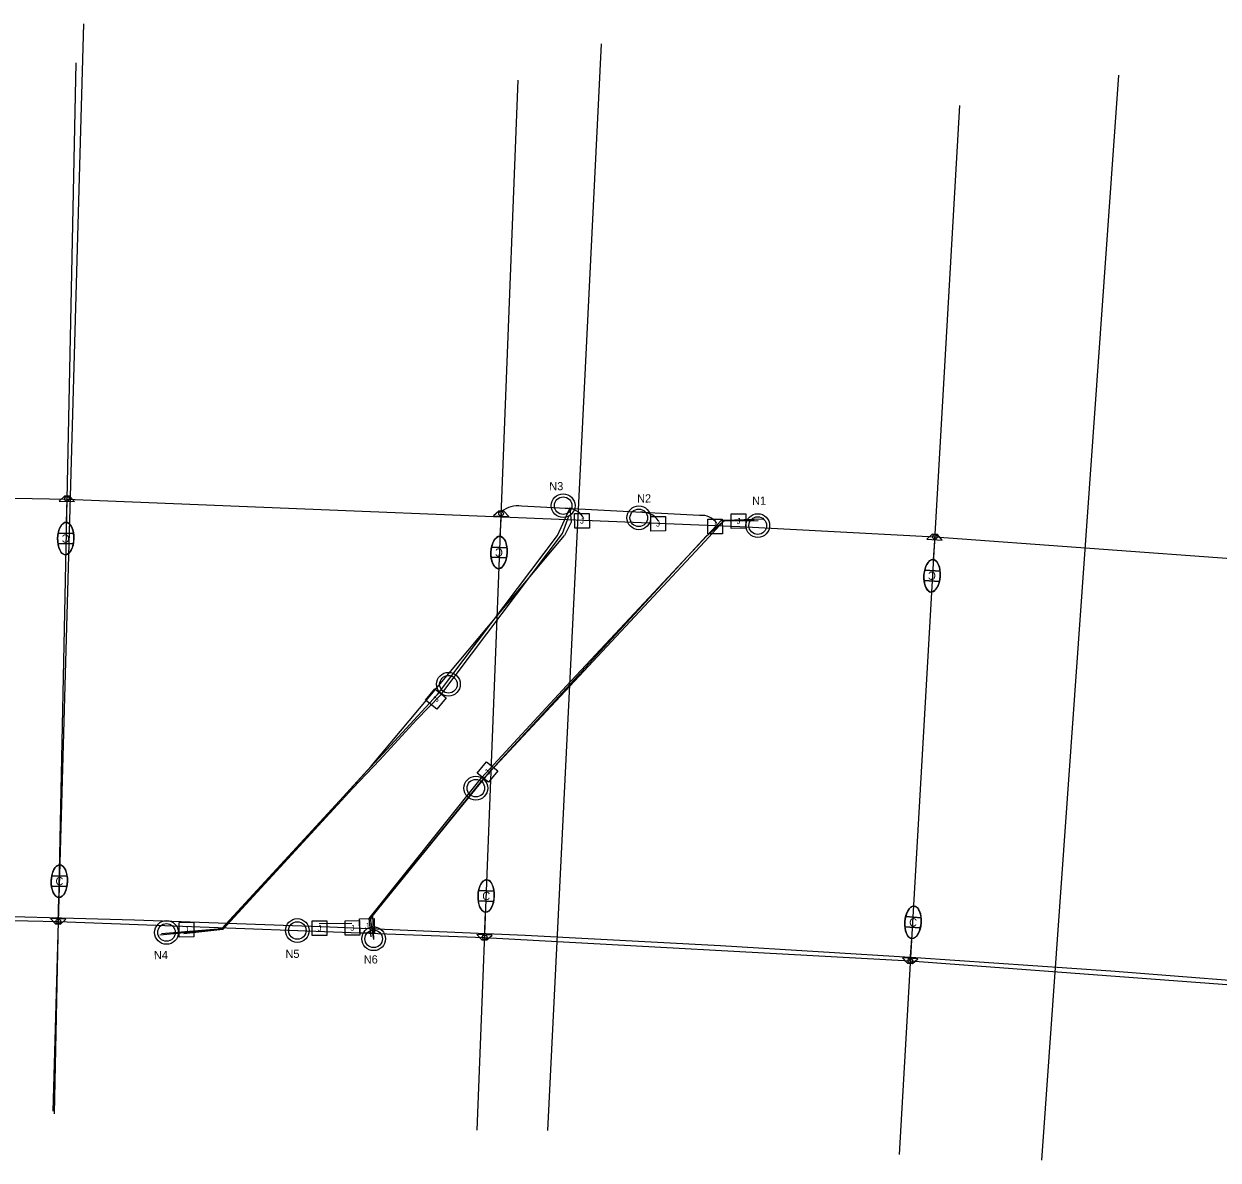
# Model space of a CAD drawing. Extents: x 915723 to 927758, y 636394 to 638609.
# Drawn here: x 923618 to 924200, y 636826 to 637381 of the extents above; entities that cross this region are included whole.
import ezdxf

# ---------------------------------------------------------------- set-up
doc = ezdxf.new("R2010")
doc.units = 0
for name, color, linetype in [('ConduitBM', 7, 'Continuous'), ('ConduitJB', 7, 'Continuous'), ('ConduitOT', 7, 'Continuous'), ('DrShaftConc', 7, 'Continuous'), ('Masonry_h', 7, 'Continuous'), ('Miscellaneous0', 7, 'Continuous'), ('Miscellaneous1', 7, 'Continuous'), ('Miscellaneous2', 7, 'Continuous'), ('PoleLight', 7, 'Continuous'), ('PullBox', 7, 'Continuous'), ('SchemElectricProp', 7, 'Continuous'), ('TextStructuresLabel', 7, 'Continuous')]:
    doc.layers.add(name, color=color, linetype=linetype)

msp = doc.modelspace()

# ---------------------------------------------------------------- linework, layer by layer
at = {"layer": 'ConduitBM'}
for p, q in [((923426.79, 637152.37), (923638.75, 637148.77)), ((923638.75, 637148.77), (923967.04, 637135.41)), ((923967.04, 637135.41), (924062.22, 637130.27)), ((924062.22, 637130.27), (924273.78, 637114.85)), ((923426.26, 636946.7), (923634.53, 636942.76)), ((923634.53, 636942.76), (923842.5, 636934.93)), ((923842.5, 636934.93), (924050.24, 636923.47)), ((924050.24, 636923.47), (924257, 636908.15))]:
    msp.add_line(p, q, dxfattribs=at)
at = {"layer": 'ConduitJB'}
for p, q in [((923947.46, 637140.78), (923860.55, 637145.32)), ((923714.85, 636938.71), (923778.24, 637007.75)), ((923761.78, 636941.71), (923777.8, 636941.86)), ((923714.85, 636938.71), (923695.74, 636936.7))]:
    msp.add_line(p, q, dxfattribs=at)
for points in [[(923778.24, 637007.75), (923791.47, 637021.58), (923809.32, 637041.11), (923821.22, 637053.21), (923880.56, 637132.02), (923883.82, 637140.88)], [(923787.24, 636935.16), (923786.18, 636944.08), (923840.97, 637012.72), (923882.53, 637057.68), (923958.1, 637138.5), (923974.12, 637138.81)]]:
    msp.add_lwpolyline(points, dxfattribs=at)
for centre, radius, start, end in [((923858.88, 637132.2), 13.23, 82.754, 127.84057), ((923882.73, 637134.92), 9.32, 26.94918, 94.93479), ((923919.61, 637133.13), 9.21, 33.12166, 96.26256), ((923948.34, 637131.61), 9.21, 34.45118, 95.45942)]:
    msp.add_arc(centre, radius, start, end, dxfattribs=at)
at = {"layer": 'DrShaftConc'}
for p, q in [((923646.82, 637380.54), (923631.93, 636850.18)), ((923899.44, 637370.74), (923873.21, 636840.82)), ((924151.8, 637355.54), (924114.23, 636826.3))]:
    msp.add_line(p, q, dxfattribs=at)
msp.add_lwpolyline([(921831.32, 636923.01), (923099.42, 636947.08), (923099.42, 636947.08), (923194.81, 636948.49), (923290.21, 636949.1), (923385.61, 636948.91), (923481.01, 636947.93), (923576.4, 636946.14), (923671.76, 636943.55), (923767.11, 636940.16), (923862.42, 636935.97), (923957.69, 636930.98), (924052.92, 636925.2), (924148.09, 636918.61), (924243.21, 636911.23)], dxfattribs=at)
at = {"layer": 'Masonry_h'}
for p, q in [((923643.12, 637361.51), (923632.6, 636848.94)), ((923858.78, 637353.12), (923838.84, 636840.91)), ((924074.19, 637340.78), (924044.87, 636829.11))]:
    msp.add_line(p, q, dxfattribs=at)
at = {"layer": 'Miscellaneous0'}
for points in [[(923684.95, 636936.92), (923714.33, 636939.24), (923819.62, 637053.46), (923878.12, 637131.01), (923884.15, 637144.22)], [(923976.03, 637138.12), (923959.14, 637137.96), (923949.96, 637128.12), (923840.83, 637011.12), (923786.72, 636944.11), (923788.4, 636933.92)]]:
    msp.add_lwpolyline(points, dxfattribs=at)
at = {"layer": 'Miscellaneous1'}
for centre, radius in [((923880.87, 637145.54), 5.79), ((923880.87, 637145.54), 4.29), ((923917.77, 637139.61), 5.79), ((923917.77, 637139.61), 4.29), ((923975.82, 637135.81), 5.79), ((923975.82, 637135.81), 4.29), ((923824.91, 637058.42), 5.79), ((923824.91, 637058.42), 4.29), ((923838.26, 637007.73), 5.79), ((923838.26, 637007.73), 4.29), ((923687.37, 636937.36), 5.79), ((923687.37, 636937.36), 4.29), ((923751.2, 636938.29), 5.79), ((923751.2, 636938.29), 4.29), ((923788.41, 636934.26), 5.79), ((923788.41, 636934.26), 4.29)]:
    msp.add_circle(centre, radius, dxfattribs=at)
at = {"layer": 'Miscellaneous2'}
for p, q in [((923642.04, 637131.88), (923634.52, 637132.09)), ((923634.52, 637132.09), (923634.52, 637132.09)), ((923787.28, 637018.48), (923881.52, 637131.04)), ((923634.38, 637127.09), (923634.38, 637127.09)), ((923634.38, 637127.09), (923641.9, 637126.88)), ((923853.5, 637125), (923845.99, 637125.37)), ((923845.99, 637125.37), (923845.99, 637125.37)), ((923845.74, 637120.38), (923845.74, 637120.38)), ((923845.74, 637120.38), (923853.25, 637120.01)), ((924064.79, 637113.55), (924057.29, 637114.08)), ((924057.29, 637114.08), (924057.29, 637114.08)), ((924056.94, 637109.09), (924056.94, 637109.09)), ((924056.94, 637109.09), (924064.43, 637108.56)), ((923787.28, 637018.48), (923725.54, 636950.91)), ((923638.89, 636964.75), (923631.38, 636964.96)), ((923638.89, 636964.75), (923638.89, 636964.75)), ((923631.24, 636959.97), (923638.75, 636959.76)), ((923638.75, 636959.76), (923638.75, 636959.76)), ((923839.44, 636952.8), (923846.95, 636952.51)), ((923847.15, 636957.5), (923839.64, 636957.8)), ((923847.15, 636957.5), (923847.15, 636957.5)), ((923846.95, 636952.51), (923846.95, 636952.51)), ((924055.48, 636944.52), (924047.99, 636945.06)), ((924055.48, 636944.52), (924055.48, 636944.52)), ((924047.63, 636940.07), (924055.13, 636939.54)), ((924055.13, 636939.54), (924055.13, 636939.54))]:
    msp.add_line(p, q, dxfattribs=at)
for points in [[(923845.67, 637016.38), (923950.81, 637130.79), (923959.72, 637138.49), (923978.4, 637139.18)], [(923884.12, 637144.57), (923884.79, 637137.42), (923881.52, 637131.04)], [(923788.5, 636933.92), (923788.07, 636945.54), (923845.67, 637016.38)], [(923684.03, 636936.15), (923714.94, 636939.16), (923725.54, 636950.91)]]:
    msp.add_lwpolyline(points, dxfattribs=at)
for centre, major_axis, start_param, end_param in [((923638.21, 637129.48), (0.22, 7.92), 1.249648, 1.891946), ((923638.21, 637129.48), (0.22, 7.92), 4.391271, 5.033538), ((923638.21, 637129.48), (0.22, 7.92), 4.391241, 4.391271), ((923849.62, 637122.69), (0.39, 7.91), 1.249648, 1.891946), ((923849.62, 637122.69), (0.39, 7.91), 4.391271, 5.033538), ((923849.62, 637122.69), (0.39, 7.91), 4.391241, 4.391271), ((924060.86, 637111.32), (0.56, 7.9), 1.249648, 1.891946), ((924060.86, 637111.32), (0.56, 7.9), 4.391271, 5.033538), ((924060.86, 637111.32), (0.56, 7.9), 4.391241, 4.391271), ((923635.06, 636962.36), (-0.22, -7.92), 4.391271, 5.033538), ((923635.06, 636962.36), (-0.22, -7.92), 4.391241, 4.391271), ((923635.06, 636962.36), (-0.22, -7.92), 1.249648, 1.891946), ((923843.3, 636955.15), (-0.31, -7.91), 4.391271, 5.033538), ((923843.3, 636955.15), (-0.31, -7.91), 4.391241, 4.391271), ((923843.3, 636955.15), (-0.31, -7.91), 1.249648, 1.891946), ((924051.56, 636942.3), (-0.56, -7.9), 4.391271, 5.033538), ((924051.56, 636942.3), (-0.56, -7.9), 4.391241, 4.391271), ((924051.56, 636942.3), (-0.56, -7.9), 1.249648, 1.891946)]:
    msp.add_ellipse(centre, major_axis=major_axis, ratio=0.5, start_param=start_param, end_param=end_param, dxfattribs=at)
at = {"layer": 'PoleLight'}
for p, q in [((923638.76, 637149.06), (923638.43, 637137.4)), ((923850.56, 637141.71), (923850.01, 637130.6)), ((923634.52, 637132.09), (923642.04, 637131.88)), ((924062.2, 637130.17), (924061.42, 637119.22)), ((923641.9, 637126.88), (923634.38, 637127.09)), ((923845.99, 637125.37), (923853.5, 637125)), ((923853.25, 637120.01), (923845.74, 637120.38)), ((924057.29, 637114.08), (924064.79, 637113.55)), ((924064.43, 637108.56), (924056.94, 637109.09)), ((923631.38, 636964.96), (923638.89, 636964.75)), ((923638.75, 636959.76), (923631.24, 636959.97)), ((923634.49, 636941.91), (923634.84, 636954.44)), ((923846.95, 636952.51), (923839.44, 636952.8)), ((923839.64, 636957.8), (923847.15, 636957.5)), ((923842.5, 636934.93), (923842.99, 636947.24)), ((924047.99, 636945.06), (924055.48, 636944.52)), ((924055.13, 636939.54), (924047.63, 636940.07)), ((924050.24, 636923.47), (924051, 636934.4))]:
    msp.add_line(p, q, dxfattribs=at)
for points in [[(923640.06, 637150.14), (923637.56, 637150.19), (923635, 637147.75), (923642.5, 637147.58)], [(923851.94, 637142.82), (923849.44, 637142.92), (923846.84, 637140.53), (923854.33, 637140.22)], [(924063.49, 637131.43), (924060.99, 637131.59), (924058.34, 637129.27), (924065.82, 637128.77)], [(923633.17, 636941.53), (923635.67, 636941.46), (923638.24, 636943.88), (923630.74, 636944.09)], [(923841.14, 636933.81), (923843.63, 636933.7), (923846.25, 636936.07), (923838.75, 636936.42)], [(924048.84, 636922.29), (924051.33, 636922.14), (924053.99, 636924.46), (924046.51, 636924.95)]]:
    msp.add_lwpolyline(points, close=True, dxfattribs=at)
for centre in [(923638.75, 637148.82), (923850.56, 637141.63), (924062.22, 637130.27), (923634.53, 636942.76), (923842.51, 636935.02), (924050.24, 636923.47)]:
    msp.add_circle(centre, 1.14, dxfattribs=at)
for centre, major_axis in [((923638.21, 637129.48), (0.22, 7.92)), ((923849.62, 637122.69), (0.39, 7.91)), ((924060.86, 637111.32), (0.56, 7.9)), ((923635.06, 636962.36), (-0.22, -7.92)), ((923843.3, 636955.15), (-0.31, -7.91)), ((924051.56, 636942.3), (-0.56, -7.9))]:
    msp.add_ellipse(centre, major_axis=major_axis, ratio=0.5, dxfattribs=at)
for centre, major_axis, start_param, end_param in [((923638.21, 637129.48), (0.22, 7.92), 0.847605, 1.249648), ((923638.21, 637129.48), (0.22, 7.92), 0, 0.847605), ((923638.21, 637129.48), (0.22, 7.92), 5.033538, 6.283185), ((923849.62, 637122.69), (0.39, 7.91), 0.847605, 1.249648), ((923849.62, 637122.69), (0.39, 7.91), 0, 0.847605), ((923849.62, 637122.69), (0.39, 7.91), 5.033538, 6.283185), ((923638.21, 637129.48), (0.22, 7.92), 1.891945, 4.391241), ((923849.62, 637122.69), (0.39, 7.91), 1.891945, 4.391241), ((924060.86, 637111.32), (0.56, 7.9), 0.847605, 1.249648), ((924060.86, 637111.32), (0.56, 7.9), 0, 0.847605), ((924060.86, 637111.32), (0.56, 7.9), 5.033538, 6.283185), ((924060.86, 637111.32), (0.56, 7.9), 1.891945, 4.391241), ((923635.06, 636962.36), (-0.22, -7.92), 1.891945, 4.391241), ((923635.06, 636962.36), (-0.22, -7.92), 5.033538, 6.283185), ((923635.06, 636962.36), (-0.22, -7.92), 0.847605, 1.249648), ((923843.3, 636955.15), (-0.31, -7.91), 1.891945, 4.391241), ((923635.06, 636962.36), (-0.22, -7.92), 0, 0.847605), ((923843.3, 636955.15), (-0.31, -7.91), 5.033538, 6.283185), ((923843.3, 636955.15), (-0.31, -7.91), 0, 0.847605), ((923843.3, 636955.15), (-0.31, -7.91), 0.847605, 1.249648), ((924051.56, 636942.3), (-0.56, -7.9), 1.891945, 4.391241), ((924051.56, 636942.3), (-0.56, -7.9), 5.033538, 6.283185), ((924051.56, 636942.3), (-0.56, -7.9), 0, 0.847605), ((924051.56, 636942.3), (-0.56, -7.9), 0.847605, 1.249648)]:
    msp.add_ellipse(centre, major_axis=major_axis, ratio=0.5, start_param=start_param, end_param=end_param, dxfattribs=at)
at = {"layer": 'PullBox'}
for p, q in [((923886.48, 637141.69), (923893.61, 637141.76)), ((923886.55, 637134.57), (923886.48, 637141.69)), ((923893.61, 637141.76), (923893.67, 637134.64)), ((923923.63, 637140.27), (923930.76, 637140.33)), ((923923.7, 637133.14), (923923.63, 637140.27)), ((923930.76, 637140.33), (923930.83, 637133.21)), ((923962.84, 637141.56), (923969.97, 637141.63)), ((923962.91, 637134.44), (923962.84, 637141.56)), ((923969.97, 637141.63), (923970.04, 637134.5)), ((923893.67, 637134.64), (923886.55, 637134.57)), ((923951.39, 637138.91), (923958.51, 637138.98)), ((923951.46, 637131.79), (923951.39, 637138.91)), ((923958.51, 637138.98), (923958.58, 637131.86)), ((923970.04, 637134.5), (923962.91, 637134.44)), ((923930.83, 637133.21), (923923.7, 637133.14)), ((923958.58, 637131.86), (923951.46, 637131.79)), ((923813.76, 637050.69), (923818.24, 637056.23)), ((923818.24, 637056.23), (923823.78, 637051.75)), ((923823.78, 637051.75), (923819.3, 637046.21)), ((923819.3, 637046.21), (923813.76, 637050.69)), ((923838.99, 637015.11), (923843.47, 637020.65)), ((923843.47, 637020.65), (923849.01, 637016.18)), ((923844.53, 637010.63), (923838.99, 637015.11)), ((923849.01, 637016.18), (923844.53, 637010.63)), ((923693.51, 636942.23), (923700.63, 636942.29)), ((923693.57, 636935.1), (923693.51, 636942.23)), ((923700.63, 636942.29), (923700.7, 636935.17)), ((923758.43, 636942.94), (923765.55, 636943.01)), ((923758.49, 636935.81), (923758.43, 636942.94)), ((923765.55, 636943.01), (923765.62, 636935.88)), ((923774.45, 636943.09), (923781.58, 636943.15)), ((923774.52, 636935.96), (923774.45, 636943.09)), ((923781.58, 636943.15), (923781.64, 636936.03)), ((923781.59, 636944.05), (923788.71, 636944.12)), ((923781.66, 636936.93), (923781.59, 636944.05)), ((923788.71, 636944.12), (923788.78, 636936.99)), ((923700.7, 636935.17), (923693.57, 636935.1)), ((923765.62, 636935.88), (923758.49, 636935.81)), ((923781.64, 636936.03), (923774.52, 636935.96)), ((923788.78, 636936.99), (923781.66, 636936.93))]:
    msp.add_line(p, q, dxfattribs=at)

# ---------------------------------------------------------------- texts
at = {"layer": 'ConduitOT'}
for rotation, p in [(0.5345, (923889.13, 637136.73)), (0.5345, (923965.49, 637136.6)), (0.5345, (923926.28, 637135.3)), (0.5345, (923954.03, 637133.95)), (51.0695, (923819.27, 637049.57)), (51.0695, (923844.5, 637014)), (0.5345, (923777.09, 636938.13)), (0.5345, (923784.23, 636939.09)), (0.5345, (923696.15, 636937.26)), (0.5345, (923761.07, 636937.98))]:
    msp.add_text('J', height=2.85, rotation=rotation, dxfattribs=at).set_placement(p)
at = {"layer": 'SchemElectricProp'}
for s, p in [('N3', (923874.12, 637152.99)), ('N2', (923916.97, 637147.03)), ('N1', (923973.07, 637145.93)), ('N4', (923681.24, 636924.3)), ('N5', (923745.41, 636924.9)), ('N6', (923783.6, 636922.16))]:
    msp.add_text(s, height=4, rotation=0.5345, dxfattribs=at).set_placement(p)
at = {"layer": 'TextStructuresLabel'}
for rotation, p in [(178.39216, (923640.14, 637131.43)), (177.16588, (923851.59, 637124.59)), (175.93959, (924062.87, 637113.18)), (358.39216, (923633.13, 636960.41)), (357.75219, (923841.35, 636953.23)), (355.93959, (924049.55, 636940.43))]:
    msp.add_text('C', height=4, rotation=rotation, dxfattribs=at).set_placement(p)

doc.saveas('drawing.dxf')
